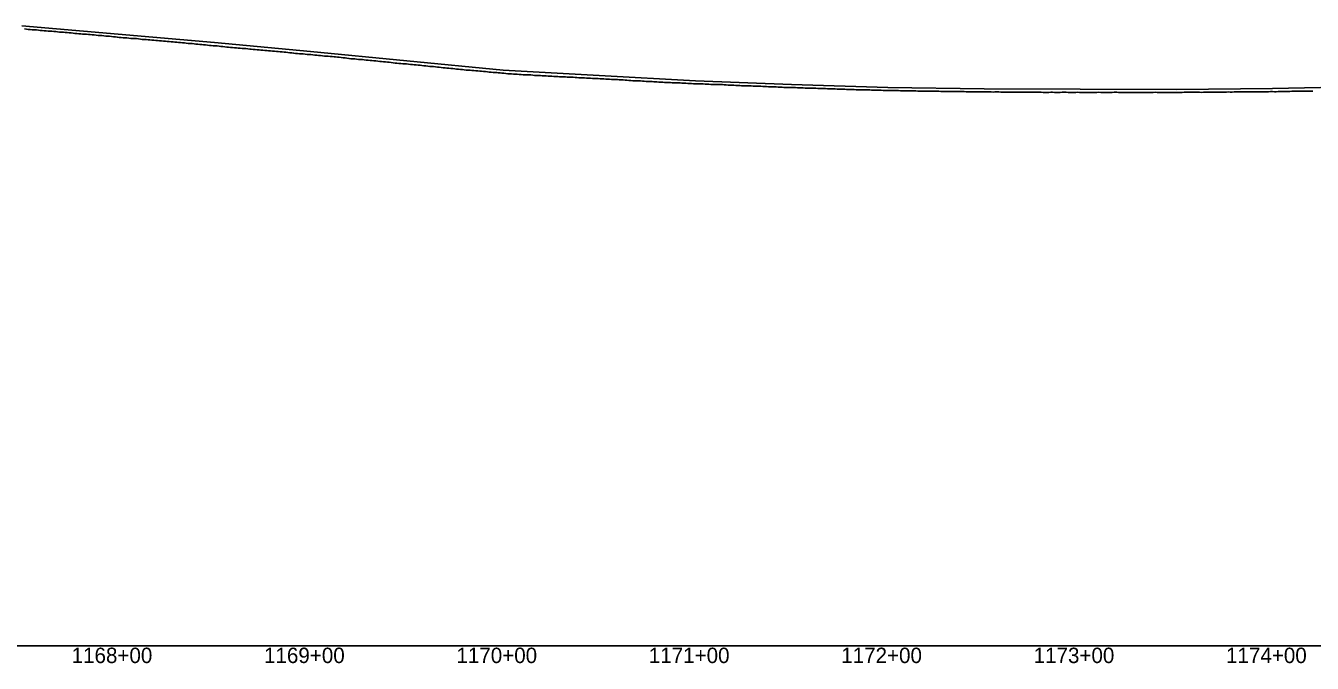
# Model space of a CAD drawing. Extents: x -3793 to 50787, y -1075 to 6138.
# Drawn here: x 4129 to 4798, y 2991 to 3322 of the extents above; entities that cross this region are included whole.
import ezdxf

# ---------------------------------------------------------------- set-up
doc = ezdxf.new("R2010")
doc.units = 0
for name, color, linetype in [('RD_DDB_Profile_EX', 7, 'Continuous'), ('RD_DDB_Profile_PR', 7, 'Continuous'), ('RD_DDB_StaTX', 7, 'Continuous'), ('RD_GPK_Profile_Cell', 7, 'Continuous')]:
    doc.layers.add(name, color=color, linetype=linetype)

msp = doc.modelspace()

# ---------------------------------------------------------------- linework, layer by layer
at = {"layer": 'RD_DDB_Profile_EX'}
for points in [[(4128.593844, 3320.69435), (4129.596708, 3320.54575), (4130.599494, 3320.395595), (4131.592334, 3320.343945), (4132.595198, 3320.293565), (4133.597984, 3320.24332), (4134.858421, 3320.14357), (4135.851502, 3320.09383), (4136.854171, 3319.94475), (4137.857031, 3319.84494), (4138.850111, 3319.74462), (4139.85278, 3319.644395), (4140.855641, 3319.54514), (4141.848717, 3319.49484), (4142.851385, 3319.444075), (4143.854254, 3319.344305), (4144.847021, 3319.29356), (4145.849991, 3319.193805), (4146.852864, 3319.09356), (4147.855528, 3319.04275), (4148.848599, 3318.943085), (4149.851474, 3318.843375), (4150.854138, 3318.79256), (4151.84711, 3318.692925), (4152.850087, 3318.59414), (4153.85275, 3318.49432), (4154.84572, 3318.394155), (4155.848696, 3318.244855), (4156.85136, 3318.144585), (4157.844332, 3318.09402), (4158.846996, 3318.043705), (4159.849969, 3317.89485), (4160.852864, 3317.894285), (4161.845605, 3317.84316), (4162.848581, 3317.74349), (4163.851481, 3317.594595), (4164.844214, 3317.54432), (4165.850586, 3317.444225), (4166.853306, 3317.344905), (4167.846208, 3317.244635), (4168.849001, 3317.194565), (4169.851786, 3317.093835), (4170.844623, 3316.94458), (4171.847415, 3316.944555), (4172.850205, 3316.89383), (4173.853002, 3316.744865), (4174.84583, 3316.645225), (4175.848693, 3316.544885), (4176.845061, 3316.445835), (4177.844245, 3316.196445), (4178.847107, 3316.195215), (4179.84984, 3316.14553), (4180.842729, 3316.09492), (4181.845522, 3315.99555), (4182.84826, 3315.94558), (4183.841144, 3315.795275), (4184.843937, 3315.74533), (4185.846679, 3315.74543), (4186.849537, 3315.645295), (4187.842352, 3315.495705), (4188.845098, 3315.39629), (4189.847956, 3315.24593), (4190.840767, 3315.24585), (4191.843517, 3315.14643), (4192.846375, 3315.045815), (4193.839181, 3314.946245), (4194.841998, 3314.845835), (4195.844795, 3314.796), (4196.837596, 3314.696455), (4197.840417, 3314.596025), (4198.843214, 3314.54623), (4199.846011, 3314.496645), (4200.838836, 3314.396255), (4201.841633, 3314.24684), (4202.84443, 3314.14723), (4203.837255, 3314.096695), (4204.840052, 3313.99711)], [(4204.840052, 3313.99711), (4205.84291, 3313.94649), (4206.835703, 3313.84699), (4207.735111, 3313.746645), (4208.738247, 3313.697035), (4209.740697, 3313.59643), (4210.737142, 3313.495845), (4211.735622, 3313.39581), (4212.738073, 3313.29514), (4213.740525, 3313.194955), (4214.738715, 3313.14345), (4215.735453, 3313.043545), (4216.737907, 3312.893405), (4217.730387, 3312.79337), (4218.732842, 3312.69295), (4219.736005, 3312.593335), (4220.738386, 3312.542535), (4221.730942, 3312.441765), (4222.741627, 3312.390465), (4223.740406, 3312.28995), (4224.743, 3312.13989), (4225.735772, 3312.039955), (4226.738458, 3311.98898), (4227.741144, 3311.93796), (4228.733822, 3311.837515), (4229.736508, 3311.68813), (4230.739462, 3311.638015), (4231.742034, 3311.536955), (4232.734826, 3311.437095), (4233.737512, 3311.28721), (4234.740198, 3311.236105), (4235.732879, 3311.08634), (4236.735565, 3311.03452), (4237.738251, 3310.9347), (4238.740938, 3310.833485), (4239.733616, 3310.73378), (4240.736306, 3310.63254), (4241.739255, 3310.582995), (4242.732085, 3310.53255), (4243.734619, 3310.432035), (4244.737306, 3310.281515), (4245.739992, 3310.231), (4246.525852, 3310.180315), (4247.528469, 3310.079775), (4248.53125, 3309.9301), (4249.524186, 3309.87877), (4250.526875, 3309.82838), (4251.529657, 3309.728725), (4252.522598, 3309.62826), (4253.52546, 3309.528735), (4254.528063, 3309.477285), (4255.530844, 3309.376725), (4256.523871, 3309.227315), (4257.526657, 3309.17582), (4258.529251, 3309.07714), (4259.532032, 3308.9766), (4260.525067, 3308.9262), (4261.527854, 3308.825655), (4262.53044, 3308.72609), (4263.523479, 3308.62664), (4264.526264, 3308.576095), (4265.52905, 3308.475555), (4266.531628, 3308.32608), (4267.524676, 3308.226605), (4268.527461, 3308.175045), (4269.530034, 3307.97769), (4270.532899, 3307.92706), (4271.525873, 3307.826655), (4272.528658, 3307.775075), (4273.531307, 3307.675525), (4274.524283, 3307.62508), (4275.527068, 3307.47567), (4276.529854, 3307.37517), (4277.532495, 3307.324515), (4278.52548, 3307.2252), (4279.528265, 3307.1247), (4280.531127, 3306.97513), (4281.52389, 3306.923555), (4282.526677, 3306.82306), (4283.529462, 3306.72254), (4284.532088, 3306.57534), (4285.525087, 3306.52374), (4286.527872, 3306.473245), (4287.530735, 3306.3725), (4288.533277, 3306.320765), (4289.523805, 3306.221555), (4290.242948, 3306.170995), (4291.245573, 3306.021685), (4292.224073, 3305.973355), (4293.241355, 3305.871515), (4294.219979, 3305.724615), (4295.246773, 3305.62266), (4296.216386, 3305.47669), (4297.242317, 3305.375965), (4298.221787, 3305.18017), (4299.238168, 3305.17599), (4300.240728, 3305.0753), (4301.220634, 3305.02596), (4302.21409, 3304.87758), (4303.239137, 3304.7758), (4304.242004, 3304.725305)], [(4304.242004, 3304.725305), (4305.212933, 3304.579115), (4306.237548, 3304.5252), (4307.218346, 3304.426895), (4308.23317, 3304.276305), (4309.232569, 3304.22676), (4310.235422, 3304.17616), (4311.238006, 3304.02672), (4312.231049, 3303.92724), (4313.233903, 3303.82666), (4314.236491, 3303.678235), (4315.229529, 3303.578715), (4316.232384, 3303.52716), (4317.234975, 3303.37867), (4318.22801, 3303.32818), (4319.230865, 3303.22863), (4320.233659, 3303.128135), (4321.22649, 3302.93157), (4322.229344, 3302.83099), (4323.232199, 3302.779545), (4324.224971, 3302.680085), (4325.227825, 3302.5805), (4326.23068, 3302.579115), (4327.223451, 3302.47867), (4328.226306, 3302.379145), (4329.22916, 3302.27871), (4330.222113, 3302.178265), (4331.224787, 3302.079645), (4332.22764, 3301.9801), (4333.220589, 3301.87967), (4334.223266, 3301.78013), (4335.226121, 3301.67976), (4336.219117, 3301.58115), (4337.221747, 3301.48063), (4338.224602, 3301.38028), (4339.217593, 3301.232435), (4340.220228, 3301.18113), (4341.223083, 3301.081605), (4342.225937, 3300.932845), (4343.218869, 3300.83163), (4344.221563, 3300.78131), (4345.224418, 3300.681805), (4346.217344, 3300.53212), (4347.220044, 3300.384105), (4348.222899, 3300.28454), (4349.215872, 3300.282885), (4350.218524, 3300.18236), (4351.221379, 3300.132125), (4352.214349, 3299.98341), (4353.217148, 3299.833595), (4354.219859, 3299.734055), (4355.212825, 3299.634605), (4356.215624, 3299.63201), (4357.21834, 3299.48456), (4358.211301, 3299.335755), (4359.2141, 3299.283915), (4360.216821, 3299.23441), (4361.209777, 3299.13497), (4362.212628, 3299.035465), (4363.215301, 3298.934295), (4364.208254, 3298.834285), (4365.207006, 3298.735985), (4366.209645, 3298.684835), (4367.202756, 3298.63543), (4368.205632, 3298.48706), (4369.208275, 3298.38655), (4370.201378, 3298.23709), (4371.204262, 3298.187565), (4372.206901, 3298.087605), (4373.209894, 3298.03642), (4374.202992, 3298.0365), (4374.778982, 3297.936705), (4375.771872, 3297.78832), (4376.774686, 3297.738785), (4377.777406, 3297.63926), (4378.770284, 3297.539805), (4379.773097, 3297.390695), (4380.775937, 3297.339755), (4381.778666, 3297.340225), (4382.771534, 3297.240775), (4383.774348, 3297.191245), (4384.77709, 3297.141725), (4385.769946, 3297.04227), (4386.772759, 3296.943065), (4387.775599, 3296.89256), (4388.768383, 3296.84277), (4389.771196, 3296.79325), (4390.77401, 3296.743995), (4391.766793, 3296.744275), (4392.769607, 3296.64452), (4393.772421, 3296.545435), (4394.765276, 3296.49523), (4395.768044, 3296.395665), (4396.770858, 3296.395915), (4397.763674, 3296.346285), (4398.766455, 3296.346765), (4399.769268, 3296.24736), (4400.772108, 3296.147), (4401.764892, 3296.09739), (4402.767705, 3296.047945), (4403.770519, 3295.948535)], [(4403.770519, 3295.948535), (4404.763313, 3295.898945), (4405.766116, 3295.89933), (4406.768929, 3295.84978), (4407.761745, 3295.799385), (4408.764553, 3295.749815), (4409.232719, 3295.75), (4409.767651, 3295.749805), (4410.761058, 3295.649455), (4411.764407, 3295.59919), (4412.767742, 3295.598815), (4413.761159, 3295.54825), (4414.76341, 3295.498645), (4415.766758, 3295.39838), (4416.770084, 3295.34804), (4417.763507, 3295.297645), (4418.766853, 3295.19731), (4419.770165, 3295.19679), (4420.763599, 3295.146575), (4421.765852, 3295.04677), (4422.7692, 3295.04621), (4423.762597, 3294.995775), (4424.765939, 3294.9454), (4425.76928, 3294.895025), (4426.762737, 3294.844015), (4427.766021, 3294.7936), (4428.768276, 3294.79406), (4429.761736, 3294.743575), (4430.765014, 3294.64316), (4431.768353, 3294.543095), (4432.761825, 3294.542265), (4433.765165, 3294.442245), (4434.767345, 3294.343045), (4435.770681, 3294.34229), (4436.76416, 3294.34142), (4437.767499, 3294.24144), (4438.770748, 3294.1906), (4439.764239, 3294.14012), (4440.767575, 3294.0402), (4441.769736, 3293.990635), (4442.76323, 3293.940175), (4443.766566, 3293.8903), (4444.769901, 3293.78993), (4445.767736, 3293.789495), (4446.771128, 3293.738545), (4447.774629, 3293.68815), (4448.766922, 3293.63909), (4449.77031, 3293.58871), (4450.773811, 3293.53895), (4451.777313, 3293.439225), (4452.770893, 3293.388835), (4453.774394, 3293.387145), (4454.777896, 3293.33677), (4455.770078, 3293.237115), (4456.334596, 3293.23656), (4457.337871, 3293.13691), (4458.331338, 3293.086495), (4459.333536, 3293.036875), (4460.336811, 3292.93727), (4461.340087, 3292.8877), (4462.333405, 3292.837335), (4463.336681, 3292.835395), (4464.339956, 3292.833375), (4465.332347, 3292.73536), (4466.335623, 3292.68417), (4467.338899, 3292.633795), (4468.332217, 3292.58423), (4469.335493, 3292.58298), (4470.338769, 3292.5326), (4471.331161, 3292.48294), (4472.334437, 3292.43348), (4473.337714, 3292.33406), (4474.340799, 3292.28181), (4475.334309, 3292.281375), (4476.337585, 3292.181995), (4477.340658, 3292.180615), (4478.333255, 3292.179955), (4479.336532, 3292.178535), (4480.339601, 3292.07916), (4481.333128, 3292.077635), (4482.336425, 3292.028285), (4483.339482, 3292.02678), (4484.332097, 3291.977155), (4485.335374, 3291.877845), (4486.338427, 3291.876315), (4487.331972, 3291.874685), (4488.335249, 3291.825415), (4489.33829, 3291.774995), (4490.340646, 3291.774265), (4491.3342, 3291.72495), (4492.337236, 3291.625745), (4493.34051, 3291.575345), (4494.334077, 3291.524885), (4495.3371, 3291.52321), (4496.340374, 3291.474085), (4497.33303, 3291.42444), (4498.336049, 3291.32534), (4499.339324, 3291.27628), (4500.340434, 3291.273185), (4501.343824, 3291.171425), (4502.34694, 3291.169625)], [(4502.34694, 3291.169625), (4503.339514, 3291.120015), (4504.342905, 3291.07234), (4505.346016, 3291.02334), (4506.349403, 3291.02154), (4507.343137, 3290.97108), (4508.346237, 3290.92068), (4509.348481, 3290.919645), (4510.342186, 3290.870655), (4511.345281, 3290.86728), (4512.348667, 3290.81684), (4513.342418, 3290.816335), (4514.345501, 3290.717445), (4515.347747, 3290.570935), (4516.341503, 3290.568945), (4517.344582, 3290.568545), (4518.347969, 3290.52133), (4519.341738, 3290.517685), (4520.345129, 3290.467285), (4521.348191, 3290.41854), (4522.350439, 3290.36893), (4523.344217, 3290.27015), (4524.347235, 3290.26814), (4525.350622, 3290.26606), (4526.344412, 3290.21732), (4527.347457, 3290.21346), (4528.349707, 3290.21389), (4529.343502, 3290.163405), (4530.346543, 3290.114745), (4531.34993, 3290.06613), (4532.343737, 3290.063885), (4533.346766, 3290.011655), (4534.349018, 3289.96389), (4534.927735, 3289.961405), (4535.919895, 3289.911765), (4536.886529, 3289.8632), (4537.925474, 3289.861805), (4538.919493, 3289.85948), (4539.922693, 3289.80904), (4540.924764, 3289.75949), (4541.92833, 3289.71091), (4542.920489, 3289.66127), (4543.924056, 3289.66085), (4544.927622, 3289.66043), (4545.919782, 3289.610795), (4546.923349, 3289.56037), (4547.925419, 3289.5108), (4548.928612, 3289.510375), (4549.884323, 3289.461815), (4550.924654, 3289.410355), (4551.927844, 3289.36184), (4552.920381, 3289.360295), (4553.92395, 3289.357965), (4554.927135, 3289.30752), (4555.92921, 3289.26179), (4556.923246, 3289.211325), (4557.925316, 3289.20982), (4558.928502, 3289.16133), (4559.922544, 3289.15891), (4560.924614, 3289.111275), (4561.927796, 3289.108915), (4562.92987, 3289.06128), (4563.884605, 3289.01279), (4564.925538, 3288.961255), (4565.929104, 3288.960855), (4566.923152, 3288.96039), (4567.924833, 3289.008835), (4568.928401, 3288.91039), (4569.930473, 3288.86276), (4570.92413, 3288.86232), (4571.927698, 3288.85993), (4572.929771, 3288.812325), (4573.923429, 3288.80987), (4574.925501, 3288.76227), (4575.92907, 3288.711885), (4576.882414, 3288.711455), (4577.924739, 3288.66186), (4578.928308, 3288.661475), (4579.93038, 3288.657855), (4580.924039, 3288.60939), (4581.927609, 3288.606935), (4582.929682, 3288.607365), (4583.923341, 3288.51098), (4584.925413, 3288.509335), (4585.928985, 3288.55688), (4586.932145, 3288.50645), (4587.924717, 3288.50476), (4588.928289, 3288.50639), (4589.929953, 3288.50682), (4590.923957, 3288.504285), (4591.927529, 3288.455935), (4592.929189, 3288.408445), (4593.932758, 3288.408035), (4594.925334, 3288.408385), (4595.928908, 3288.36008), (4596.930566, 3288.31047), (4597.924642, 3288.310025), (4598.928216, 3288.26176), (4599.929869, 3288.26213), (4600.93344, 3288.25964), (4601.926021, 3288.25997)], [(4601.926021, 3288.25997), (4602.929174, 3288.25958), (4603.889654, 3288.25921), (4604.925264, 3288.20956), (4605.928414, 3288.163465), (4606.930488, 3288.16382), (4607.927176, 3288.209165), (4608.921131, 3288.208755), (4609.923267, 3288.209145), (4610.926715, 3288.206625), (4611.918932, 3288.15697), (4612.92238, 3288.1566), (4613.92589, 3288.15619), (4615.0035, 3288.15713), (4616.006915, 3288.154595), (4617.009089, 3288.10717), (4618.001699, 3288.05756), (4619.004751, 3288.057145), (4620.006866, 3288.007595), (4621.009039, 3288.00801), (4622.001227, 3288.00839), (4623.004701, 3288.007985), (4624.006816, 3287.95843), (4625.008987, 3288.008845), (4626.002478, 3288.00633), (4627.004649, 3287.956765), (4628.006763, 3287.95927), (4629.008532, 3287.959685), (4630.002426, 3287.95721), (4631.004595, 3287.957645), (4632.006708, 3287.862105), (4633.008484, 3287.910525), (4634.002371, 3287.95809), (4635.004538, 3287.91248), (4636.006651, 3287.86486), (4637.0002, 3287.81443), (4638.002313, 3287.81093), (4639.004479, 3287.861345), (4640.006212, 3287.859885), (4641.000141, 3287.81132), (4642.002254, 3287.85986), (4643.004418, 3287.81408), (4644.007463, 3287.76563), (4645.00008, 3287.812165), (4646.002192, 3287.86075), (4647.003987, 3287.863035), (4648.007409, 3287.812655), (4649.000017, 3287.86116), (4650.002128, 3287.861635), (4651.005238, 3287.81305), (4651.99779, 3287.815265), (4652.999951, 3287.86205), (4654.001707, 3287.86431), (4655.00518, 3287.813895), (4655.997724, 3287.814285), (4656.999882, 3287.76647), (4658.001992, 3287.718645), (4659.005422, 3287.7183), (4659.997953, 3287.71865), (4660.999718, 3287.719055), (4662.003148, 3287.766975), (4663.005259, 3287.7674), (4663.997781, 3287.71947), (4664.999555, 3287.71987), (4666.002986, 3287.71953), (4666.995505, 3287.718205), (4667.997657, 3287.7653), (4669.000761, 3287.76657), (4670.002872, 3287.76702), (4670.995382, 3287.67067), (4671.997489, 3287.62268), (4673.000602, 3287.7191), (4674.002714, 3287.717925), (4674.995216, 3287.7199), (4675.997323, 3287.768765), (4677.000446, 3287.71838), (4678.002559, 3287.671945), (4678.995052, 3287.673835), (4679.998531, 3287.671925), (4681.000334, 3287.62233), (4682.002447, 3287.71819), (4682.994931, 3287.720095), (4683.998369, 3287.62274), (4685.000182, 3287.67165), (4685.992662, 3287.720545), (4686.9961, 3287.76867), (4687.99821, 3287.72061), (4689.000032, 3287.721055), (4689.992504, 3287.721445), (4690.995982, 3287.721035), (4691.998092, 3287.72291), (4692.999923, 3287.723335), (4693.992386, 3287.7237), (4694.995826, 3287.771935), (4695.997936, 3287.771), (4696.310607, 3287.770485), (4697.312586, 3287.6751), (4698.315898, 3287.673355), (4699.308486, 3287.672335), (4700.311801, 3287.72055), (4701.314833, 3287.718725)], [(4701.314833, 3287.718725), (4702.307426, 3287.573355), (4703.310771, 3287.572965), (4704.313027, 3287.67059), (4705.306394, 3287.671545), (4706.309708, 3287.67116), (4707.311965, 3287.67303), (4708.315278, 3287.671225), (4709.307589, 3287.72019), (4710.310901, 3287.71835), (4711.314213, 3287.66939), (4712.306811, 3287.66979), (4713.309836, 3287.71939), (4714.312126, 3287.66983), (4715.315437, 3287.66943), (4716.309095, 3287.764535), (4717.31106, 3287.717975), (4718.31437, 3287.669035), (4719.306973, 3287.669435), (4720.310286, 3287.71756), (4721.313302, 3287.717145), (4722.315563, 3287.71763), (4723.309221, 3287.670135), (4724.311478, 3287.667635), (4725.314494, 3287.715725), (4726.308187, 3287.66822), (4727.310445, 3287.668685), (4728.313455, 3287.668285), (4729.315718, 3287.71875), (4730.309378, 3287.71829), (4731.312688, 3287.766365), (4732.314647, 3287.76534), (4733.321225, 3287.76634), (4734.323341, 3287.76831), (4735.326506, 3287.813325), (4736.320401, 3287.765875), (4737.322474, 3287.76789), (4738.325678, 3287.815915), (4739.327799, 3287.7679), (4740.32165, 3287.71899), (4741.325162, 3287.76702), (4742.326928, 3287.81593), (4743.320827, 3287.86385), (4744.322944, 3287.86433), (4745.3261, 3287.768605), (4746.329608, 3287.81502), (4747.322122, 3287.76698), (4748.325588, 3287.81659), (4749.327395, 3287.86545), (4750.321253, 3287.81497), (4751.324765, 3287.86453), (4752.326568, 3287.86498), (4753.33003, 3287.81618), (4754.322548, 3287.913365), (4755.32574, 3287.866125), (4756.329202, 3287.865735), (4757.321725, 3287.91449), (4758.325191, 3287.914075), (4759.32699, 3287.91453), (4760.320902, 3287.915655), (4761.324367, 3287.916915), (4762.326163, 3287.915695), (4763.329671, 3287.96362), (4764.322152, 3288.012405), (4765.325664, 3287.96194), (4766.231508, 3287.96174), (4767.224002, 3287.962145), (4768.227555, 3288.06168), (4769.230723, 3288.012935), (4770.223222, 3287.96499), (4771.226775, 3288.01119), (4772.230276, 3288.01076), (4773.232022, 3288.05955), (4774.225943, 3288.060735), (4775.228023, 3288.06121), (4776.231238, 3288.10733), (4777.225163, 3288.108515), (4778.227243, 3288.062425), (4779.230401, 3288.062015), (4780.232486, 3288.11247), (4781.226463, 3288.16196), (4782.229963, 3288.11155), (4783.231701, 3288.11027), (4784.225683, 3288.10974), (4785.229182, 3288.15931), (4786.230917, 3288.20978), (4787.234413, 3288.26112), (4788.226931, 3288.311505), (4789.230484, 3288.261065), (4790.233628, 3288.308865), (4791.226151, 3288.311035), (4792.229704, 3288.312385), (4793.232843, 3288.358375), (4794.23493, 3288.358845), (4795.228869, 3288.406535), (4796.230952, 3288.40882), (4797.234146, 3288.361975), (4798.228088, 3288.411525)]]:
    msp.add_lwpolyline(points, dxfattribs=at)
at = {"layer": 'RD_DDB_Profile_PR'}
msp.add_lwpolyline([(4127.33, 3322.3585), (4177.33, 3317.925), (4227.33, 3313.559), (4277.33, 3308.9345), (4327.33, 3304.068), (4377.33, 3299.2835), (4427.33, 3296.4155), (4477.33, 3293.7805), (4527.33, 3291.8135), (4577.33, 3290.29), (4627.33, 3289.5575), (4677.33, 3289.303), (4727.33, 3289.2685), (4777.33, 3289.7035), (4827.33, 3290.805)], dxfattribs=at)
at = {"layer": 'RD_GPK_Profile_Cell'}
msp.add_line((1000, 3000), (46549.603806, 3000), dxfattribs=at)

# ---------------------------------------------------------------- texts
at = {"layer": 'RD_DDB_StaTX'}
for s, p in [('1168+00', (4153.125471, 2991)), ('1168+00', (4153.125471, 2991)), ('1169+00', (4253.125471, 2991)), ('1169+00', (4253.125471, 2991)), ('1170+00', (4353.125471, 2991)), ('1170+00', (4353.125471, 2991)), ('1171+00', (4453.125471, 2991)), ('1171+00', (4453.125471, 2991)), ('1172+00', (4553.125471, 2991)), ('1172+00', (4553.125471, 2991)), ('1173+00', (4653.125471, 2991)), ('1173+00', (4653.125471, 2991)), ('1174+00', (4753.125471, 2991)), ('1174+00', (4753.125471, 2991))]:
    msp.add_text(s, height=8, dxfattribs=at).set_placement(p)

doc.saveas('drawing.dxf')
